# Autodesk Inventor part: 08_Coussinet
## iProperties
Created: 2000-12
Part Number: 08_Coussinet
Material: Par défaut
Document SubType Name: Modélisation
Designer: Administrateur
Control State: 0
Master: False
Checked Out: False
Shininess: 20.0
Length Units: 11269
Angle Units: 11279
Time Units: 11290
Mass Units: 11283
Length Display Precision: 3
Angle Display Precision: 2
Density: 0.0
Volumn: 0.0
Area: 0.0
PropertySet Name: Model Information
Author: Administrateur
